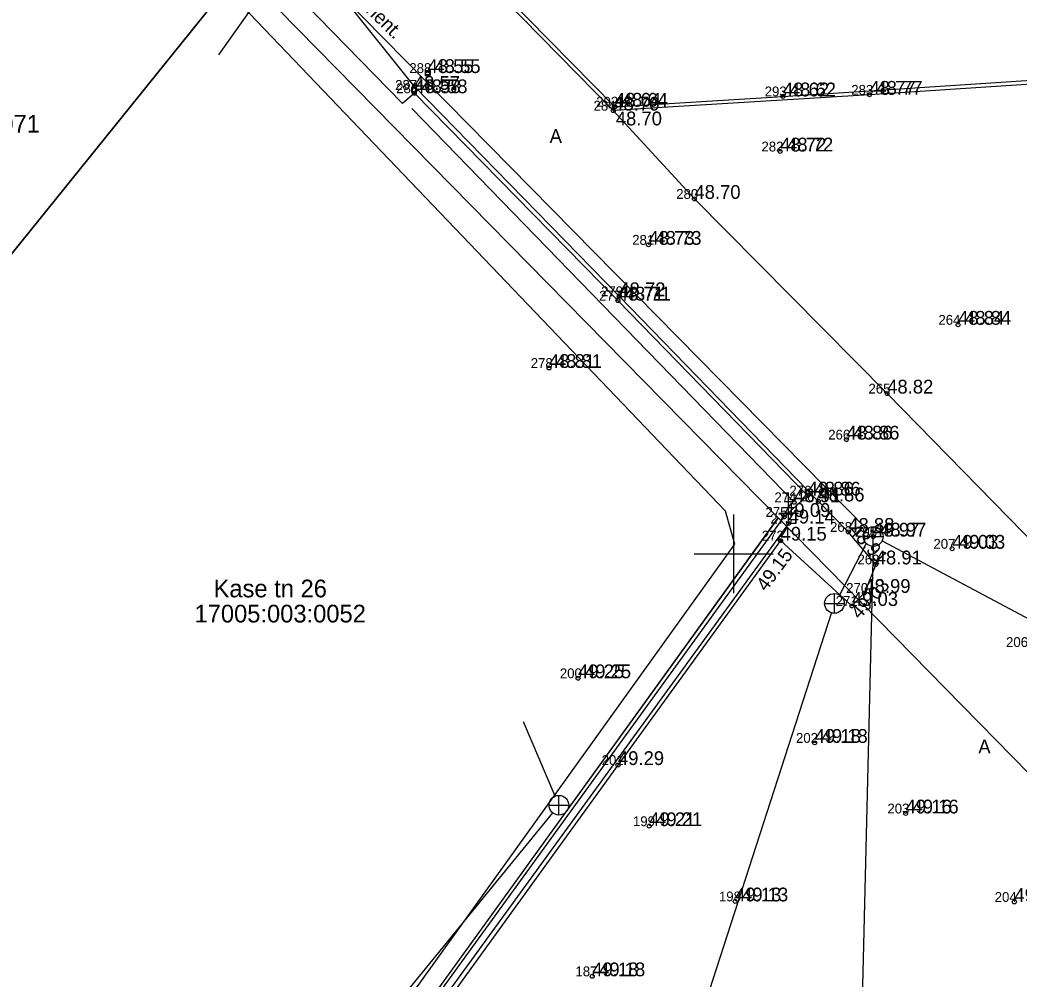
# Model space of a CAD drawing. Extents: x 640876 to 641418, y 6455595 to 6456085.
# Drawn here: x 641063.8 to 641114.5, y 6455928.4 to 6455977.1 of the extents above; entities that cross this region are included whole.
import ezdxf

# ---------------------------------------------------------------- set-up
doc = ezdxf.new("R2010")
doc.units = 0
for name, color, linetype in [('AED', 7, 'Continuous'), ('KKAEV', 7, 'Continuous'), ('KORGUS', 7, 'Continuous'), ('KTRASS', 7, 'Continuous'), ('MOOTKORG', 7, 'Continuous'), ('MOOTMPUNKT', 7, 'Continuous'), ('MOOTNR', 7, 'Continuous'), ('MOOTPIIR', 7, 'Continuous'), ('PIIR', 7, 'Continuous'), ('PUU', 7, 'Continuous'), ('SKTRASS', 7, 'Continuous'), ('TEE', 7, 'Continuous'), ('VORK', 7, 'Continuous')]:
    doc.layers.add(name, color=color, linetype=linetype)

msp = doc.modelspace()

# ---------------------------------------------------------------- linework, layer by layer
at = {"layer": 'AED'}
for p, q in [((641084.336, 6455974.539), (641084.336, 6455974.289)), ((641084.336, 6455974.539), (641084.586, 6455974.539)), ((641084.586, 6455974.539), (641084.586, 6455974.289)), ((641084.336, 6455974.289), (641084.586, 6455974.289)), ((641083.64, 6455973.684), (641083.64, 6455973.434)), ((641083.64, 6455973.684), (641083.89, 6455973.684)), ((641083.64, 6455973.434), (641083.89, 6455973.434)), ((641083.89, 6455973.684), (641083.89, 6455973.434)), ((641103.073, 6455952.612), (641083.671, 6455972.616))]:
    msp.add_line(p, q, dxfattribs=at)
for points in [[(641083.796, 6455973.39), (641083.187, 6455972.863), (641076.75, 6455979.46), (641073.84, 6455975.34)], [(641149.47, 6455968.396), (641146.41, 6455975.887), (641122.837, 6455974.363), (641106.897, 6455973.309), (641093.89, 6455972.505), (641088.371, 6455978.142)], [(641063.184, 6455882.915), (641067.225, 6455888.43), (641061.101, 6455894.64), (641102.569, 6455951.872), (641103.756, 6455952.954), (641094.123, 6455962.857), (641083.796, 6455973.39)]]:
    msp.add_lwpolyline(points, dxfattribs=at)
at = {"layer": 'KKAEV'}
for p, q in [((641107.089, 6455950.372), (641107.089, 6455951.372)), ((641106.589, 6455950.872), (641107.589, 6455950.872)), ((641104.62, 6455947.48), (641105.62, 6455947.48)), ((641105.12, 6455946.98), (641105.12, 6455947.98)), ((641091.13, 6455936.73), (641091.13, 6455937.73)), ((641090.63, 6455937.23), (641091.63, 6455937.23))]:
    msp.add_line(p, q, dxfattribs=at)
for centre in [(641107.089, 6455950.872), (641105.12, 6455947.48), (641091.13, 6455937.23)]:
    msp.add_circle(centre, 0.5, dxfattribs=at)
at = {"layer": 'KORGUS'}
for centre in [(641084.461, 6455974.414), (641083.796, 6455973.39), (641106.897, 6455973.309), (641102.503, 6455973.228), (641093.89, 6455972.505), (641093.974, 6455972.705), (641102.363, 6455970.43), (641095.676, 6455965.69), (641094.123, 6455962.857), (641111.398, 6455961.629), (641090.626, 6455959.435), (641105.726, 6455955.8), (641103.756, 6455952.954), (641102.383, 6455950.666), (641107.089, 6455950.872), (641111.095, 6455950.255), (641107.214, 6455949.459), (641106.005, 6455947.351), (641092.103, 6455943.678), (641104.117, 6455940.397), (641108.732, 6455936.811), (641095.715, 6455936.167), (641100.079, 6455932.344), (641114.254, 6455932.318), (641092.82, 6455928.541)]:
    msp.add_circle(centre, 0.1, dxfattribs=at)
at = {"layer": 'KTRASS'}
for points in [[(641106.77, 6455951.257), (641077.988, 6455980.501)], [(641107.541, 6455950.658), (641125.909, 6455940.865)], [(641106.735, 6455950.518), (641105.375, 6455947.897)], [(641107.089, 6455950.372), (641106.418, 6455923.157)], [(641104.971, 6455947.019), (641098.222, 6455926.122)], [(641090.94, 6455937.692), (641089.337, 6455941.467)], [(641090.812, 6455936.841), (641051.218, 6455888.362)]]:
    msp.add_lwpolyline(points, dxfattribs=at)
at = {"layer": 'MOOTMPUNKT'}
for centre in [(641084.461, 6455974.414), (641083.765, 6455973.559), (641083.796, 6455973.39), (641106.897, 6455973.309), (641102.503, 6455973.228), (641093.89, 6455972.505), (641093.974, 6455972.705), (641102.363, 6455970.43), (641098.01, 6455968.023), (641095.676, 6455965.69), (641094.123, 6455962.857), (641094.195, 6455963.079), (641111.398, 6455961.629), (641090.626, 6455959.435), (641107.796, 6455958.136), (641105.726, 6455955.8), (641103.073, 6455952.612), (641103.756, 6455952.954), (641104.302, 6455952.658), (641102.569, 6455951.872), (641102.791, 6455951.536), (641105.82, 6455951.112), (641102.383, 6455950.666), (641107.089, 6455950.872), (641111.095, 6455950.255), (641107.214, 6455949.459), (641106.639, 6455948.012), (641106.005, 6455947.351), (641092.103, 6455943.678), (641104.117, 6455940.397), (641094.127, 6455939.27), (641108.732, 6455936.811), (641095.715, 6455936.167), (641100.079, 6455932.344), (641114.254, 6455932.318), (641092.82, 6455928.541)]:
    msp.add_circle(centre, 0.1, dxfattribs=at)
at = {"layer": 'MOOTPIIR'}
msp.add_lwpolyline([(641060.916, 6455895.936), (641100.061, 6455950.482), (641099.586, 6455952.159), (641069.132, 6455984.035), (641066.132, 6455988.623), (641076.463, 6456005.049), (641230.642, 6456010.048), (641237.36, 6455995.24), (641237.24, 6455992.81), (641236.258, 6455990.888), (641229.041, 6455971.315), (641203.026, 6455909.57), (641225.257, 6455906.847), (641239.512, 6455898.491), (641200.195, 6455851.697), (641192.016, 6455859.099), (641169.785, 6455829.138), (641192.025, 6455807.568), (641252.96, 6455758.075), (641231.388, 6455736.74), (641191.474, 6455775.975), (641152.419, 6455787.914), (641136.351, 6455788.307), (641049.066, 6455856.043)], dxfattribs=at)
at = {"layer": 'PIIR'}
for points in [[(641222.58, 6455998.61), (641237.36, 6455995.24), (641235.34, 6455991.29), (641228.11, 6455971.68), (641220.5, 6455953.19), (641213.41, 6455936.25), (641201.58, 6455908.74), (641224.93, 6455905.88), (641191.87, 6455860.58), (641157.02, 6455885.66), (641160.91, 6455891.99), (641102.26, 6455951.82), (641074.95, 6455979.64), (641084.84, 6455991.92)], [(641074.95, 6455979.64), (641102.26, 6455951.82), (641075.14, 6455914.24), (641043, 6455940)], [(641098.62, 6455818.85), (641093.41, 6455823.22), (641084.65, 6455830.08), (641067.32, 6455843.61), (641055.55, 6455852.8), (641061.31, 6455859.9), (641051.68, 6455867.61), (641067, 6455888.54), (641060.97, 6455894.57), (641075.14, 6455914.24), (641087.11, 6455930.82), (641102.26, 6455951.82), (641160.91, 6455891.99), (641157.02, 6455885.66), (641139.49, 6455869), (641124.05, 6455849.81)]]:
    msp.add_lwpolyline(points, close=True, dxfattribs=at)
msp.add_lwpolyline([(641061.51, 6455993.34), (641084.84, 6455991.92), (641074.95, 6455979.64), (641043, 6455940)], dxfattribs=at)
at = {"layer": 'PUU'}
for p, q in [((641102.791, 6455951.536), (641102.791, 6455953.111)), ((641102.941, 6455952.636), (641102.641, 6455952.636)), ((641103.091, 6455952.336), (641102.491, 6455952.336)), ((641103.291, 6455952.036), (641102.291, 6455952.036)), ((641103.151, 6455951.536), (641102.791, 6455951.536))]:
    msp.add_line(p, q, dxfattribs=at)
msp.add_lwpolyline([(641102.791, 6455951.536), (641061.687, 6455894.955)], dxfattribs=at)
at = {"layer": 'TEE'}
for points in [[(641107.214, 6455949.459), (641105.82, 6455951.112), (641104.302, 6455952.658), (641094.195, 6455963.079), (641083.782, 6455973.751), (641080.443, 6455977.904), (641077.332, 6455981.101), (641073.264, 6455982.442), (641070.4, 6455982.608), (641069.377, 6455981.48)], [(641088.438, 6455978.34), (641093.974, 6455972.705), (641102.503, 6455973.228), (641118.732, 6455974.289), (641132.709, 6455975.218), (641148.246, 6455976.21), (641160.465, 6455968.928), (641160.995, 6455968.496)], [(641123.495, 6455927.37), (641122.34, 6455938.576), (641121.847, 6455943.77), (641116.257, 6455949.486), (641107.796, 6455958.136), (641098.01, 6455968.023), (641093.89, 6455972.505)], [(641107.214, 6455949.459), (641106.639, 6455948.012), (641106.005, 6455947.351), (641102.383, 6455950.666), (641094.127, 6455939.27), (641083.533, 6455924.608), (641064.463, 6455898.315)]]:
    msp.add_lwpolyline(points, dxfattribs=at)
at = {"layer": 'VORK'}
for p, q in [((641100, 6455952), (641100, 6455948)), ((641098, 6455950), (641102, 6455950))]:
    msp.add_line(p, q, dxfattribs=at)

# ---------------------------------------------------------------- texts
at = {"layer": 'KORGUS'}
for s, p in [('48.55', (641084.811, 6455974.414)), ('48.58', (641084.146, 6455973.39)), ('48.62', (641102.853, 6455973.228)), ('48.77', (641107.247, 6455973.309)), ('48.64', (641094.324, 6455972.705)), ('48.70', (641094.019, 6455971.755)), ('48.72', (641102.713, 6455970.43)), ('48.73', (641096.026, 6455965.69)), ('48.71', (641094.473, 6455962.857)), ('48.84', (641111.748, 6455961.629)), ('48.81', (641090.976, 6455959.435)), ('48.86', (641106.076, 6455955.8)), ('48.86', (641104.106, 6455952.954)), ('48.97', (641107.439, 6455950.872)), ('49.03', (641111.445, 6455950.255)), ('49.25', (641092.453, 6455943.678)), ('49.18', (641104.467, 6455940.397)), ('49.16', (641109.082, 6455936.811)), ('49.21', (641096.065, 6455936.167)), ('49.13', (641100.429, 6455932.344)), ('49.18', (641093.17, 6455928.541))]:
    msp.add_text(s, height=0.7, dxfattribs=at).set_placement(p)
for s, rotation, p in [('48.91', 312.057, (641105.814, 6455951.148)), ('49.15', 53.3981, (641101.647, 6455948.048)), ('49.03', 47.5319, (641106.388, 6455946.631))]:
    msp.add_text(s, height=0.7, rotation=rotation, dxfattribs=at).set_placement(p)
at = {"layer": 'MOOTKORG'}
for s, p in [('48.55', (641084.461, 6455974.414)), ('48.57', (641083.765, 6455973.559)), ('48.58', (641083.796, 6455973.39)), ('48.62', (641102.503, 6455973.228)), ('48.77', (641106.897, 6455973.309)), ('48.64', (641093.974, 6455972.705)), ('48.70', (641093.89, 6455972.505)), ('48.72', (641102.363, 6455970.43)), ('48.70', (641098.01, 6455968.023)), ('48.73', (641095.676, 6455965.69)), ('48.72', (641094.195, 6455963.079)), ('48.71', (641094.123, 6455962.857)), ('48.84', (641111.398, 6455961.629)), ('48.81', (641090.626, 6455959.435)), ('48.82', (641107.796, 6455958.136)), ('48.86', (641105.726, 6455955.8)), ('48.86', (641103.756, 6455952.954)), ('48.91', (641103.073, 6455952.612)), ('48.86', (641104.302, 6455952.658)), ('49.09', (641102.569, 6455951.872)), ('49.14', (641102.791, 6455951.536)), ('48.88', (641105.82, 6455951.112)), ('48.97', (641107.089, 6455950.872)), ('49.15', (641102.383, 6455950.666)), ('49.03', (641111.095, 6455950.255)), ('48.91', (641107.214, 6455949.459)), ('48.99', (641106.639, 6455948.012)), ('49.03', (641106.005, 6455947.351)), ('49.25', (641092.103, 6455943.678)), ('49.18', (641104.117, 6455940.397)), ('49.29', (641094.127, 6455939.27)), ('49.16', (641108.732, 6455936.811)), ('49.21', (641095.715, 6455936.167)), ('49.13', (641100.079, 6455932.344)), ('49.17', (641114.254, 6455932.318)), ('49.18', (641092.82, 6455928.541))]:
    msp.add_text(s, height=0.7, dxfattribs=at).set_placement(p)
at = {"layer": 'MOOTNR'}
for s, p in [('288', (641083.536, 6455974.414)), ('287', (641082.815, 6455973.559)), ('286', (641082.871, 6455973.39)), ('293', (641101.578, 6455973.228)), ('283', (641105.972, 6455973.309)), ('284', (641092.89, 6455972.505)), ('292', (641093.024, 6455972.705)), ('282', (641101.413, 6455970.43)), ('280', (641097.086, 6455968.023)), ('281', (641094.851, 6455965.69)), ('277', (641093.173, 6455962.857)), ('279', (641093.27, 6455963.079)), ('264', (641110.398, 6455961.629)), ('278', (641089.701, 6455959.435)), ('265', (641106.846, 6455958.136)), ('266', (641104.801, 6455955.8)), ('274', (641102.073, 6455952.612)), ('276', (641102.831, 6455952.954)), ('267', (641103.352, 6455952.658)), ('275', (641101.619, 6455951.872)), ('273', (641101.866, 6455951.536)), ('268', (641104.895, 6455951.112)), ('272', (641101.433, 6455950.666)), ('208', (641106.164, 6455950.872)), ('207', (641110.145, 6455950.255)), ('269', (641106.289, 6455949.459)), ('270', (641105.714, 6455948.012)), ('271', (641105.18, 6455947.351)), ('206', (641113.831, 6455945.263)), ('200', (641091.178, 6455943.678)), ('202', (641103.167, 6455940.397)), ('201', (641093.302, 6455939.27)), ('203', (641107.808, 6455936.811)), ('199', (641094.89, 6455936.167)), ('198', (641099.254, 6455932.344)), ('204', (641113.254, 6455932.318)), ('187', (641091.97, 6455928.541))]:
    msp.add_text(s, height=0.5, dxfattribs=at).set_placement(p)
at = {"layer": 'PIIR'}
msp.add_text('17005:003:0071', height=0.9, rotation=360, dxfattribs=at).set_placement((641056.082, 6455971.39))
for s, p in [('Kase tn 26', (641073.597, 6455947.786)), ('17005:003:0052', (641072.63, 6455946.51))]:
    msp.add_text(s, height=0.9, dxfattribs=at).set_placement(p)
at = {"layer": 'SKTRASS'}
msp.add_text('orient.', height=0.7, rotation=315.6107, dxfattribs=at).set_placement((641080.924, 6455977.91))
at = {"layer": 'TEE'}
for p in [(641090.659, 6455970.866), (641112.424, 6455939.858)]:
    msp.add_text('A', height=0.7, dxfattribs=at).set_placement(p)

doc.saveas('drawing.dxf')
